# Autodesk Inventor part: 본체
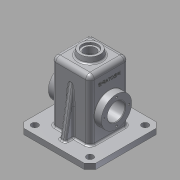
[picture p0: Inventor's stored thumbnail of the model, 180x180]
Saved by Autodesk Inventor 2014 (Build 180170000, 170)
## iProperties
Created: 2016-02
Part Number: 본체
Material: 알루미늄 6061
Document SubType Name: Modeling
Designer: USER
Density: 2.71 g/cm^3
Appearance: 알루미늄 - 평지
Mass: 932.506 g
Surface Area: 1045.17 cm^2
Volume: 344.098 cm^3
Author: USER
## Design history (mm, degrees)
sketch "스케치4"
  geometry: L1 (-35, 35)-(35, 35); L2 (35, 35)-(35, -35); L3 (35, -35)-(-35, -35); L4 (-35, -35)-(-35, 35); 3 further points
  constraints: 8 end point, 2 midpoint, 2 parallel, 1 horizontal, 1 horizontal alignment, 1 perpendicular, 1 vertical alignment
  dimensions: "d8" = 70 distance between parallel lines of L2 L4; "d9" = 70 distance between parallel lines of L3 L1
extrude "돌출3" new body sketch "스케치4" distance "d10" = 120; taper "d11" = 0 deg
feature "쉘1" dims "d12" = 5
sketch "스케치5"
  geometry: L1 (35, 35)-(-35, 35) reference; L2 (-35, 35)-(-35, -35) reference; L3 (-35, -35)-(35, -35) reference; L4 (35, -35)-(35, 35) reference; L5 (-65, 65)-(65, 65); L6 (65, 65)-(65, -65); L7 (65, -65)-(-65, -65); L8 (-65, -65)-(-65, 65); 3 further points
  constraints: 8 end point, 2 midpoint, 2 parallel, 1 horizontal, 1 horizontal alignment, 1 perpendicular, 1 vertical alignment
  dimensions: "d13" = 130 distance between parallel lines of L6 L8; "d14" = 130 distance between parallel lines of L7 L5
extrude "돌출4" join sketch "스케치5" distance "d15" = 10; taper "d16" = 0 deg
fillet "모깎기1" dims "d17" = 8
sketch "스케치6"
  geometry: L1 (0, 0)-(0, 60) reference; C1 r 27.5 at (55, 30); 2 further points
  constraints: 1 centre point, 1 horizontal alignment, 1 midpoint
  dimensions: "d18" = 55 diameter of C1; "d19" = 55 distance from line of L1 C1.centre
extrude "돌출5" join sketch "스케치6" distance "d20" = 7; taper "d21" = 0 deg
chamfer "모따기1" distance "d22" = 7; stored, may be unused: second distance "d23" = 2, angle "d24" = 135 deg
chamfer "모따기2" distance "d25" = 7; stored, may be unused: second distance "d26" = 2, angle "d27" = 135 deg
sketch "스케치7"
  geometry: C1 r 27.5 at (-57, 27); 1 further point
  constraints: 1 centre point, 1 horizontal alignment
  dimensions: "d28" = 55 diameter of C1; "d29" = 55 distance of point (-112, 27) C1.centre
extrude "돌출6" join sketch "스케치7" distance "d30" = 13; taper "d31" = 0 deg
sketch "스케치8"
  geometry: C1 r 27.5 at (0, 0) reference; C2 r 16 at (0, 0); 1 further point
  constraints: 1 centre point, 1 coincident
  dimensions: "d32" = 32 diameter of C2
extrude "돌출7" cut sketch "스케치8" stored distance "d33" = 13; taper "d34" = 0 deg
sketch "스케치9"
  geometry: C1 r 16 at (0, 0) reference; 2 further points
  constraints: 1 horizontal alignment
  dimensions: "d35" = 22.5 distance of C1.centre point (22.5, 0)
hole "구멍1" sketch "스케치9" at (22.5, 0) diameter "d36" = 3.459; stored, may be unused: countersink angle "d40" = 90 deg, drill point angle "d42" = 118 deg; dims "d37" = 8, "d38" = 4, "d39" = 2, "d41" = 10
chamfer "모따기3" distance "d46" = 1; stored, may be unused: second distance "d47" = 2, angle "d48" = 45 deg
chamfer "모따기4" distance "d49" = 1; stored, may be unused: second distance "d50" = 2, angle "d51" = 45 deg
chamfer "모따기5" distance "d52" = 10; stored, may be unused: second distance "d53" = 2, angle "d54" = 45 deg
sketch "스케치10"
  geometry: L1 (55, 65)-(-55, 65) reference; L2 (-65, 55)-(-65, -55) reference; L3 (-55, -65)-(55, -65) reference; L4 (65, -55)-(65, 55) reference; C1 r 6 at (-50, 50); C2 r 6 at (50, 50); C3 r 6 at (-50, -50); C4 r 6 at (50, -50); 1 further point
  constraints: 4 centre point
  dimensions: "d56" = 12 diameter of C1; "d57" = 12 diameter of C2; "d58" = 12 diameter of C3; "d59" = 12 diameter of C4; "d60" = 15 distance from line of L2 C1.centre; "d61" = 15 distance from line of C1.centre L1; "d62" = 15 distance from line of L1 C2.centre; "d63" = 15 distance from line of L4 C2.centre; "d64" = 15 distance from line of L3 C3.centre; "d65" = 15 distance from line of L2 C3.centre; "d66" = 15 distance from line of L4 C4.centre; "d67" = 15 distance from line of L3 C4.centre
extrude "돌출8" cut sketch "스케치10" stored distance "d68" = 10; taper "d69" = 0 deg
fillet "모깎기2" dims "d70" = 3
sketch "스케치11"
  geometry: L1 (30, 0)-(30, 112) reference; L2 (35, 112)-(35, 10) reference; L3 (55, 10)-(-55, 10) reference; L4 (55, 10)-(65, 10) reference; L5 (55, 0)-(-55, 0) reference; L6 (65, 0)-(55, 0) reference; L7 (-35, 10)-(-35, 112) reference; L8 (-30, 112)-(-30, 0) reference; L9 (35, 95.069)-(50, 10); L10 (65, 10)-(65, 0) reference; L11 (-35, 95.069)-(-50, 10); L12 (-65, 0)-(-65, 10) reference; 1 further point
  constraints: 4 end point, 4 point on line
  dimensions: "d71" = 15 distance from line of L10 L9.end; "d72" = 10 deg angle of L10 L9; "d73" = 15 distance from line of L11.end L12; "d74" = 10 deg angle of L11 L12
feature "리브1" dims "d75" = 1, "d76" = 10, "d77" = 0, "d78" = 0, "d79" = 1, "d80" = 1
feature "리브2" dims "d81" = 1, "d82" = 10, "d83" = 0, "d84" = 0, "d85" = 1, "d86" = 1
fillet "모깎기3" dims "d87" = 3
fillet "모깎기4" dims "d88" = 3
fillet "모깎기5" dims "d89" = 3
sketch "스케치12"
  geometry: C1 r 20 at (0, 0); 1 further point
  constraints: 1 centre point, 1 coincident
  dimensions: "d90" = 40 diameter of C1
extrude "돌출9" join sketch "스케치12" distance "d91" = 10; taper "d92" = 0 deg
chamfer "모따기6" distance "d93" = 10; stored, may be unused: second distance "d94" = 2, angle "d95" = 10 deg
sketch "스케치13"
  geometry: C1 r 18.237 at (0, 0) reference; C2 r 10.5 at (0, 0)
  constraints: 1 centre point, 1 coincident
  dimensions: "d96" = 21 diameter of C2
extrude "돌출10" cut sketch "스케치13" distance "d97" = 30; taper "d98" = 0 deg
sketch "스케치14"
  geometry: C1 r 10.5 at (0, 0) reference; C2 r 18.237 at (0, 0) reference; C3 r 14 at (0, 0)
  constraints: 1 centre point, 1 coincident
  dimensions: "d99" = 28 diameter of C3
extrude "돌출11" cut sketch "스케치14" distance "d100" = 4; taper "d101" = 0 deg
fillet "모깎기6" dims "d102" = 3
sketch "스케치15"
  geometry: L1 (99, 62)-(0, 62) reference; L2 (-18, 8.763)-(-18, 45.237) reference; 2 further points
  constraints: 1 other
  dimensions: "d103" = 35 distance from line of L1 point (12, 27); "d104" = 30 distance from line of L2 point (12, 27)
feature "엠보싱1" sketch "스케치15" dims "d13" = 130, "d14" = 130, "d105" = 0.5, "d106" = 0
fillet "모깎기7" dims "d107" = 0.5
fillet "모깎기8" dims "d108" = 0.5
node "솔리드2"
mirror "대칭1"
mirror "대칭2"
pattern_circular "원형 패턴1" dims angle "d44" = 360 deg
mirror "대칭3"
